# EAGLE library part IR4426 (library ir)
DUAL LOW SIDE DRIVER Source: ID4426.pdf
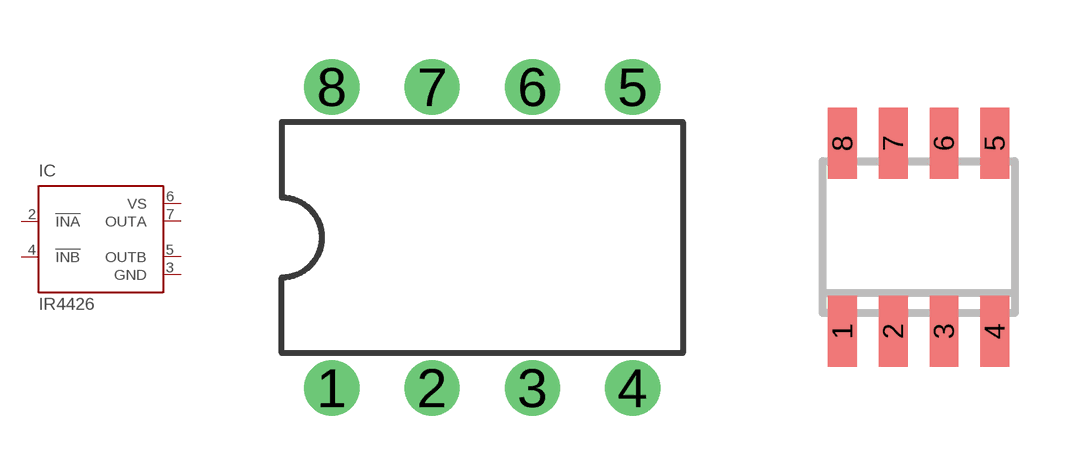
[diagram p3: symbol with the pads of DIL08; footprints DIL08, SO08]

Designator prefix IC

## IR4426 (MF: INTERNATIONAL RECTIFIER(IR); MPN: IR4426PBF; OC_FARNELL: 1023265; OC_NEWARK: 19K8460)  [DIL08]
2  !INA  in
3  GND  pwr
4  !INB  in
5  OUTB  out
6  VS  pwr
7  OUTA  out

## IR4426S (MF: INTERNATIONAL RECTIFIER(IR); MPN: IR4426S; OC_FARNELL: 1023266; OC_NEWARK: 27C6913)  [SO08]
Pads as for DIL08

## Footprint DIL08 (pad centres in mm)
Dual In Line Package
drill 0.8 pad 1.4 round: 1 -3.81,-3.81; 2 -1.27,-3.81; 3 1.27,-3.81; 4 3.81,-3.81; 5 3.81,3.81; 6 1.27,3.81; 7 -1.27,3.81; 8 -3.81,3.81

## Footprint SO08 (pad centres in mm)
8 Lead SOIC Data Sheet No. PD60212 Rev A Source: www.irf.com .. ir2520.pdf
smd 0.72 x 1.78: 1 -1.905,-2.35; 2 -0.635,-2.35; 3 0.635,-2.35; 4 1.905,-2.35; 5 1.905,2.35; 6 0.635,2.35; 7 -0.635,2.35; 8 -1.905,2.35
